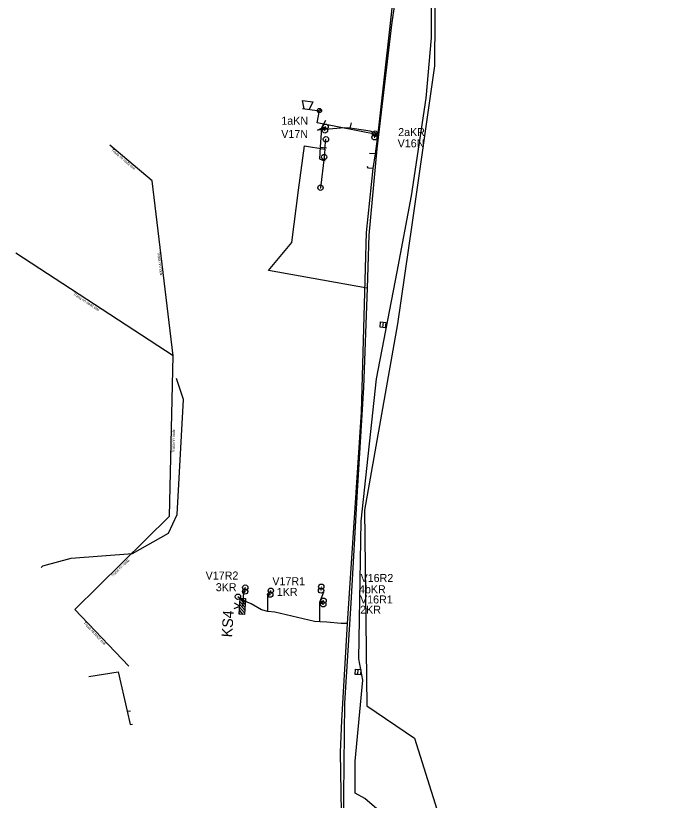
# Model space of a CAD drawing. Extents: x -748507 to -687366, y -1057342 to -1024924.
# Drawn here: x -745239.2 to -745118.4, y -1029857.9 to -1029710.8 of the extents above; entities that cross this region are included whole.
import ezdxf

# ---------------------------------------------------------------- set-up
doc = ezdxf.new("R2010")
doc.units = 0
for name, color, linetype in [('6kV - SŽDC', 7, 'Continuous'), ('DK + TKK - SŽDC', 7, 'Continuous'), ('kanalizace ČD', 7, 'Continuous'), ('Sděl MK - SŽDC', 7, 'Continuous'), ('Telefonica O2', 7, 'Continuous'), ('TK+DOK_Pha Holešovice - Kralupy', 7, 'Continuous'), ('Vedení NN - SŽDC', 7, 'Continuous'), ('ČEZ Distribuce - NN', 7, 'Continuous')]:
    doc.layers.add(name, color=color, linetype=linetype)

msp = doc.modelspace()

# ---------------------------------------------------------------- linework, layer by layer
at = {"layer": '6kV - SŽDC'}
for points in [[(-745175.61, -1029856.57), (-745175.62, -1029850.6), (-745174.15, -1029835.37), (-745174.91, -1029831.39), (-745174.49, -1029805.55), (-745171.58, -1029778.93), (-745167.7, -1029758.81), (-745165.03, -1029744.61), (-745162.32, -1029726.27), (-745161.32, -1029714.99), (-745161.36, -1029690.67)], [(-745164.1, -1029873.44), (-745168.39, -1029862.17), (-745173.78, -1029857.58), (-745175.61, -1029856.57)]]:
    msp.add_lwpolyline(points, dxfattribs=at)
at = {"layer": 'DK + TKK - SŽDC'}
for p, q in [((-745181.19, -1029731.64), (-745181.09, -1029731.64)), ((-745181.31, -1029732.33), (-745181.21, -1029732.33)), ((-745171.92, -1029732.92), (-745171.82, -1029732.92)), ((-745172.02, -1029733.61), (-745171.92, -1029733.61)), ((-745196.23, -1029818.03), (-745196.13, -1029818.03)), ((-745182.05, -1029818.58), (-745181.95, -1029818.58)), ((-745181.99, -1029817.88), (-745181.89, -1029817.88)), ((-745197.61, -1029819.74), (-745197.51, -1029819.74)), ((-745196.18, -1029820.68), (-745196.74, -1029820.04)), ((-745196.26, -1029818.76), (-745196.16, -1029818.76)), ((-745196.15, -1029820.15), (-745196.21, -1029820.07)), ((-745191.56, -1029819.34), (-745191.46, -1029819.34)), ((-745191.45, -1029818.62), (-745191.35, -1029818.62)), ((-745196.29, -1029822.26), (-745197.22, -1029821.2)), ((-745196.25, -1029821.73), (-745197.18, -1029820.67)), ((-745196.22, -1029821.2), (-745197.15, -1029820.14)), ((-745181.63, -1029821.17), (-745181.53, -1029821.17)), ((-745181.57, -1029820.49), (-745181.47, -1029820.49)), ((-745197.12, -1029823.02), (-745197.32, -1029822.79)), ((-745196.59, -1029823.05), (-745197.29, -1029822.26)), ((-745196.32, -1029822.79), (-745197.25, -1029821.73))]:
    msp.add_line(p, q, dxfattribs=at)
for points in [[(-745171.29, -1029733.14), (-745167.85, -1029702.05), (-745165.42, -1029676.12), (-745164.34, -1029662.47), (-745164.16, -1029649.05), (-745163.34, -1029629.31), (-745164.82, -1029616.99), (-745166, -1029592.69), (-745167.3, -1029583.63), (-745168.01, -1029581.22)], [(-745182.64, -1029732.28), (-745181.91, -1029731.9), (-745181.09, -1029730.38)], [(-745176.53, -1029731.93), (-745177.6, -1029731.82), (-745182.64, -1029732.28)], [(-745181.26, -1029732.33), (-745181.91, -1029731.9), (-745181.14, -1029731.64)], [(-745176.53, -1029731.93), (-745176.29, -1029730.9)], [(-745181.91, -1029731.9), (-745182.15, -1029735.44), (-745182.31, -1029737.65), (-745181.69, -1029737.91), (-745181.22, -1029737.99)], [(-745171.26, -1029733), (-745172.81, -1029732.48), (-745175.73, -1029732.03), (-745176.53, -1029731.93)], [(-745171.87, -1029732.92), (-745171.26, -1029733), (-745171.97, -1029733.61)], [(-745182.15, -1029735.44), (-745181, -1029735.6)], [(-745171.77, -1029736.74), (-745172.91, -1029736.63)], [(-745172.21, -1029739.44), (-745173.07, -1029739.43), (-745173.32, -1029739.11)], [(-745178.09, -1029842.97), (-745177.04, -1029824.78), (-745174.4, -1029785.15)], [(-745196.58, -1029820.45), (-745196.47, -1029819.03), (-745196.18, -1029818.03)], [(-745177.04, -1029824.78), (-745178.23, -1029824.74), (-745180.93, -1029824.52), (-745182.24, -1029824.47), (-745183.21, -1029824.37), (-745190.63, -1029822.67), (-745191.96, -1029822.52), (-745193.14, -1029822.23), (-745195.1, -1029821.06), (-745196.58, -1029820.45), (-745197.56, -1029819.74)], [(-745197.34, -1029823), (-745197.14, -1029820.01), (-745196.14, -1029820.08), (-745196.34, -1029823.07), (-745197.34, -1029823)], [(-745196.47, -1029819.03), (-745196.21, -1029818.76)], [(-745191.96, -1029822.52), (-745191.97, -1029819.59), (-745191.4, -1029818.62)], [(-745191.97, -1029819.59), (-745191.51, -1029819.34)], [(-745182.22, -1029820.79), (-745181.5, -1029818.83)], [(-745198.27, -1029821.94), (-745197.24, -1029821.51), (-745198.2, -1029820.94)], [(-745196.58, -1029820.45), (-745196.74, -1029821.54)], [(-745182.24, -1029824.47), (-745182.22, -1029820.79)], [(-745181.52, -1029820.49), (-745182.22, -1029820.79), (-745181.58, -1029821.17)], [(-745167.34, -1029951.52), (-745173.92, -1029916.83), (-745176.87, -1029884.7), (-745177.89, -1029876.83), (-745178.05, -1029867.68), (-745178.32, -1029848.88), (-745178.09, -1029842.97)]]:
    msp.add_lwpolyline(points, dxfattribs=at)
msp.add_lwpolyline([(-745197.34, -1029823), (-745197.14, -1029820.01), (-745196.14, -1029820.08), (-745196.34, -1029823.07)], close=True, dxfattribs=at)
for centre in [(-745181.14, -1029731.64), (-745181.26, -1029732.33), (-745171.97, -1029733.61), (-745171.87, -1029732.92), (-745196.21, -1029818.76), (-745196.18, -1029818.03), (-745191.4, -1029818.62), (-745182, -1029818.58), (-745181.94, -1029817.88), (-745197.56, -1029819.74), (-745191.51, -1029819.34), (-745181.52, -1029820.49), (-745181.58, -1029821.17)]:
    msp.add_circle(centre, 0.5, dxfattribs=at)
at = {"layer": 'kanalizace ČD'}
for points in [[(-745170.44, -1029769.29), (-745170.94, -1029769.23), (-745170.82, -1029768.24), (-745169.83, -1029768.36), (-745169.95, -1029769.35), (-745170.44, -1029769.29), (-745170.32, -1029768.3)], [(-745175.08, -1029834.35), (-745175.58, -1029834.32), (-745175.52, -1029833.33), (-745174.52, -1029833.38), (-745174.58, -1029834.38), (-745175.08, -1029834.35), (-745175.02, -1029833.35)]]:
    msp.add_lwpolyline(points, dxfattribs=at)
at = {"layer": 'Sděl MK - SŽDC'}
for p, q in [((-745185.18, -1029728.27), (-745185.49, -1029726.72)), ((-745185.49, -1029726.72), (-745183.5, -1029726.96)), ((-745183.5, -1029726.96), (-745184.19, -1029728.39)), ((-745185.47, -1029728.23), (-745182.7, -1029728.57)), ((-745182.24, -1029728.99), (-745182.67, -1029728.45)), ((-745181.93, -1029728.74), (-745182.35, -1029728.2))]:
    msp.add_line(p, q, dxfattribs=at)
for points in [[(-745178.05, -1029867.68), (-745178.32, -1029848.88), (-745178.09, -1029842.97), (-745177.04, -1029824.78), (-745174.4, -1029785.15), (-745173.46, -1029751.45), (-745172.21, -1029739.44), (-745171.77, -1029736.74), (-745171.29, -1029733.14), (-745171.26, -1029733), (-745167.85, -1029702.05)], [(-745154.8, -1029995.58), (-745158.55, -1029985.33), (-745160.94, -1029978.6), (-745161.2, -1029977.47), (-745162, -1029974.04), (-745167.34, -1029951.52), (-745173.92, -1029916.83), (-745176.87, -1029884.7), (-745177.89, -1029876.83), (-745178.05, -1029867.68), (-745178.32, -1029848.88), (-745178.09, -1029842.97), (-745177.04, -1029824.78), (-745174.4, -1029785.15), (-745173.46, -1029751.45), (-745172.21, -1029739.44), (-745171.77, -1029736.74), (-745171.29, -1029733.14), (-745182.69, -1029730.9), (-745182.3, -1029728.6)]]:
    msp.add_lwpolyline(points, dxfattribs=at)
msp.add_circle((-745182.3, -1029728.6), 0.401, dxfattribs=at)
msp.add_circle((-745182.3, -1029728.6), 0.401, dxfattribs=at)
at = {"layer": 'Telefonica O2'}
for points in [[(-745220.87, -1029429.41), (-745214.3, -1029442.96), (-745211, -1029444.54), (-745187.13, -1029500), (-745183.05, -1029509.48), (-745160.74, -1029591.85), (-745159.57, -1029600.59), (-745159.23, -1029610.21), (-745160.42, -1029674.95), (-745160.74, -1029720.24), (-745165, -1029750), (-745167.66, -1029768.6), (-745173.87, -1029803.5), (-745173.44, -1029840.22)], [(-745234.46, -1029814.24), (-745234.1, -1029813.97), (-745228.83, -1029812.51), (-745217.34, -1029811.67), (-745210.57, -1029807.86), (-745208.93, -1029804.3), (-745207.76, -1029782.78), (-745209.07, -1029778.81)], [(-745225.5, -1029834.69), (-745219.98, -1029833.85), (-745218.3, -1029841.18), (-745217.7, -1029841.11)], [(-745173.44, -1029840.22), (-745164.48, -1029846.23), (-745160.31, -1029859.58)], [(-745173.44, -1029840.22), (-745164.48, -1029846.23), (-745160.31, -1029859.58), (-745148.54, -1029887.59), (-745124.79, -1029947.94), (-745120.12, -1029958.65), (-745119.95, -1029959.15), (-745118.42, -1029961.25), (-745122.72, -1029970.77)], [(-745218.3, -1029841.18), (-745217.77, -1029843.7), (-745217.35, -1029843.61)]]:
    msp.add_lwpolyline(points, dxfattribs=at)
at = {"layer": 'TK+DOK_Pha Holešovice - Kralupy'}
msp.add_lwpolyline([(-745178.05, -1029867.68), (-745178.32, -1029848.88), (-745178.09, -1029842.97), (-745177.04, -1029824.78), (-745174.4, -1029785.15), (-745173.46, -1029751.45), (-745172.21, -1029739.44), (-745171.77, -1029736.74), (-745171.26, -1029733), (-745167.85, -1029702.05)], dxfattribs=at)
msp.add_lwpolyline([(-745178.05, -1029867.68), (-745178.32, -1029848.88), (-745178.09, -1029842.97), (-745177.04, -1029824.78), (-745174.4, -1029785.15), (-745173.46, -1029751.45), (-745172.21, -1029739.44), (-745171.77, -1029736.74), (-745171.26, -1029733), (-745167.85, -1029702.05)], dxfattribs=at)
at = {"layer": 'Vedení NN - SŽDC'}
for p, q in [((-745181.12, -1029733.99), (-745181.02, -1029733.99)), ((-745181.45, -1029737.32), (-745181.35, -1029737.32)), ((-745182.15, -1029743.08), (-745182.05, -1029743.08))]:
    msp.add_line(p, q, dxfattribs=at)
for points in [[(-745165.62, -1029690.5), (-745168.77, -1029712.56), (-745171.52, -1029735.76), (-745173.03, -1029751.99), (-745173.37, -1029761.89), (-745191.81, -1029758.57), (-745187.44, -1029753.36), (-745186.24, -1029743.5), (-745185.08, -1029735.25), (-745181.27, -1029735.84), (-745181.07, -1029733.99)], [(-745181.27, -1029735.84), (-745181.4, -1029737.32), (-745182.1, -1029743.08)], [(-745173.37, -1029761.89), (-745174.01, -1029780.53), (-745175.2, -1029799.98), (-745176.42, -1029820.94), (-745177.6, -1029839.69), (-745177.76, -1029856.97), (-745177.63, -1029867.83), (-745176.96, -1029872.66), (-745176.52, -1029886.62), (-745173.8, -1029916.09), (-745169.43, -1029941.02), (-745163.95, -1029964.33), (-745161.62, -1029973.88), (-745157.15, -1029988.43), (-745149.7, -1030009.49), (-745143.54, -1030023.69), (-745134.94, -1030039.47), (-745133.28, -1030040.89), (-745154.51, -1030053.6)]]:
    msp.add_lwpolyline(points, dxfattribs=at)
for centre in [(-745181.07, -1029733.99), (-745181.4, -1029737.32), (-745182.1, -1029743.08)]:
    msp.add_circle(centre, 0.5, dxfattribs=at)
at = {"layer": 'ČEZ Distribuce - NN'}
for points in [[(-745213.61, -1029741.79), (-745221.56, -1029735.07)], [(-745209.69, -1029774.61), (-745213.61, -1029741.79)], [(-745209.69, -1029774.61), (-745239.21, -1029755.35)], [(-745210.38, -1029804.64), (-745209.69, -1029774.61)], [(-745228.1, -1029822.12), (-745210.38, -1029804.64)], [(-745228.1, -1029822.12), (-745218, -1029832.79)]]:
    msp.add_lwpolyline(points, dxfattribs=at)

# ---------------------------------------------------------------- texts
at = {"layer": 'DK + TKK - SŽDC'}
for s, p in [('1aKN', (-745189.43, -1029731.26)), ('V17N', (-745189.45, -1029733.75)), ('2aKR', (-745167.54, -1029733.39)), ('V16N', (-745167.64, -1029735.5)), ('V17R2', (-745203.62, -1029816.52)), ('V16R2', (-745174.59, -1029816.98)), ('V17R1', (-745191.12, -1029817.58)), ('3KR', (-745201.72, -1029818.71)), ('1KR', (-745190.29, -1029819.58)), ('4bKR', (-745174.89, -1029819.1)), ('V16R1', (-745174.69, -1029821.01)), ('2KR', (-745174.66, -1029822.92))]:
    msp.add_text(s, height=1.5, dxfattribs=at).set_placement(p)
msp.add_text('KS4', height=2, rotation=86.2056, dxfattribs=at).set_placement((-745198.67, -1029827.4))
at = {"layer": 'ČEZ Distribuce - NN'}
for s, rotation, p in [('Trasa nn nadz izol', 319.773, (-745221.36, -1029736.09)), ('Trasa nn nadz', 276.8277, (-745212.67, -1029755.15)), ('Trasa nn nadz izol', 326.8716, (-745228.48, -1029763.13)), ('Trasa nn nadz', 88.6685, (-745209.46, -1029792.79)), ('Trasa nn nadz', 44.6093, (-745221.03, -1029816.06)), ('Trasa nn nadz izol', 313.4419, (-745226.54, -1029824.71))]:
    msp.add_text(s, height=0.5, rotation=rotation, dxfattribs=at).set_placement(p)

doc.saveas('drawing.dxf')
